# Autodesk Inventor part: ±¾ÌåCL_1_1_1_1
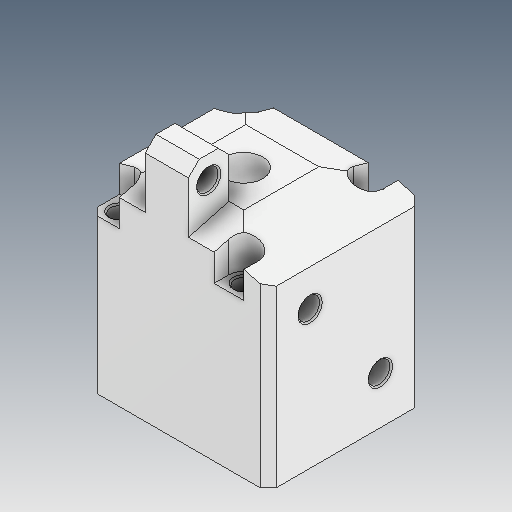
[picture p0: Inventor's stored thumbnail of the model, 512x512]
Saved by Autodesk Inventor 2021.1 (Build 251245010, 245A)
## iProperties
Created: 2021-05
Part Number: ±¾ÌåCL_1_1_1_1
Material: Ogólny
Document SubType Name: Modeling
Designer: user
Density: 1 g/cm^3
Appearance: Domyślna
Author: user
Revision Number: ÈÎºÎ
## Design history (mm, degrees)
feature "ÊäÈë1"
node "Bryła1"
